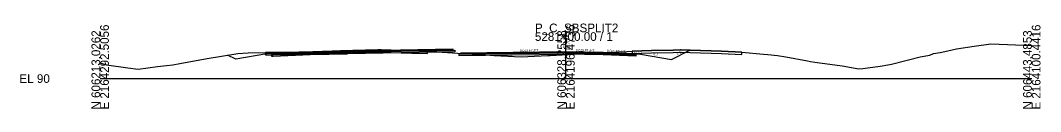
# Model space of a CAD drawing. Extents: x -26 to 1303, y -10 to 12033.
# Drawn here: x -25.7 to 302.8, y 990.3 to 1017.8 of the extents above; entities that cross this region are included whole.
import ezdxf

# ---------------------------------------------------------------- set-up
doc = ezdxf.new("R2010")
doc.units = 0
for name, color, linetype in [('RD_GPK_XS_Cell', 7, 'Continuous'), ('RD_XS_Base', 7, 'Continuous'), ('RD_XS_ExGround', 7, 'Continuous'), ('RD_XS_ExPaveRet', 7, 'Continuous'), ('RD_XS_Greenside', 7, 'Continuous'), ('RD_XS_Pave', 7, 'Continuous'), ('RD_XS_PaveOvlay_CP', 7, 'Continuous'), ('RD_XS_TieSlope', 7, 'Continuous'), ('RD_XS_TX_Elev_EX', 7, 'Continuous'), ('RD_XS_TX_Elev_PR', 7, 'Continuous'), ('RD_XS_TX_ShdSlope', 7, 'Continuous'), ('RD_XS_TX_Slope', 7, 'Continuous')]:
    doc.layers.add(name, color=color, linetype=linetype)

msp = doc.modelspace()

# ---------------------------------------------------------------- linework, layer by layer
at = {"layer": 'RD_GPK_XS_Cell'}
for p, q in [((150, 1000), (150, 1015)), ((0, 1000), (150, 1000)), ((150, 1000), (300, 1000))]:
    msp.add_line(p, q, dxfattribs=at)
at = {"layer": 'RD_XS_Base'}
for p, q in [((79.67, 1008.52), (113.67, 1009.2)), ((114.17, 1008.71), (79.67, 1008.02)), ((79.67, 1008.02), (79.67, 1008.68)), ((79.67, 1008.68), (79.67, 1008.68)), ((79.67, 1008.68), (79.67, 1008.68)), ((79.67, 1008.68), (79.67, 1008.52)), ((103.67, 1009), (103.67, 1009)), ((103.67, 1009), (103.67, 1009)), ((113.67, 1009.2), (113.67, 1009.2)), ((114.17, 1009.21), (114.17, 1008.71)), ((114.17, 1009.18), (114.17, 1009.18)), ((55.67, 1007.8), (55.17, 1007.78)), ((55.17, 1007.78), (55.17, 1007.78)), ((55.17, 1007.78), (55.17, 1007.28)), ((55.17, 1007.28), (55.67, 1007.3)), ((67.67, 1008.28), (55.67, 1007.8)), ((55.67, 1007.8), (55.67, 1007.8)), ((55.67, 1007.3), (67.67, 1007.78)), ((55.67, 1007.3), (55.67, 1007.3)), ((79.67, 1008.52), (67.67, 1008.28)), ((67.67, 1008.28), (67.67, 1008.28)), ((67.67, 1007.78), (79.67, 1008.02)), ((67.67, 1007.78), (67.67, 1007.78)), ((79.67, 1008.52), (79.67, 1008.52)), ((79.67, 1008.02), (79.67, 1008.52)), ((79.67, 1008.52), (79.67, 1008.52)), ((79.67, 1008.52), (79.67, 1008.52)), ((79.67, 1008.02), (79.67, 1008.02)), ((103.67, 1008.5), (103.67, 1008.5)), ((103.67, 1008.5), (103.67, 1008.5)), ((115.5, 1007.93), (115.5, 1007.43)), ((115.5, 1007.92), (115.5, 1007.92)), ((115.5, 1007.43), (149.99, 1007.88)), ((150, 1008.38), (116, 1007.94)), ((116, 1007.94), (116, 1007.94)), ((150, 1007.88), (150, 1008.54)), ((150, 1008.54), (150, 1008.54)), ((150, 1008.54), (150, 1008.54)), ((150, 1008.54), (150, 1008.38)), ((150, 1007.88), (150, 1008.38)), ((150, 1008.38), (150, 1008.38)), ((150, 1008.38), (150, 1008.38)), ((150, 1008.38), (150, 1008.38)), ((150, 1008.38), (162, 1008.14)), ((150, 1008.38), (150, 1008.38)), ((150, 1007.88), (150, 1007.88)), ((162, 1007.64), (150, 1007.88)), ((150, 1007.88), (150, 1007.88)), ((162, 1008.14), (162, 1008.14)), ((162, 1008.14), (172, 1007.74)), ((172.5, 1007.22), (162, 1007.64)), ((162, 1007.64), (162, 1007.64)), ((172, 1007.74), (172, 1007.74)), ((172, 1007.74), (172.5, 1007.72)), ((172.5, 1007.72), (172.5, 1007.72)), ((172.5, 1007.72), (172.5, 1007.22))]:
    msp.add_line(p, q, dxfattribs=at)
at = {"layer": 'RD_XS_ExGround'}
msp.add_lwpolyline([(0, 1005.15), (2.06, 1004.47), (8.93, 1003.52), (12.28, 1003.04), (18.45, 1003.86), (21.39, 1004.24), (23.36, 1004.5), (25.69, 1004.93), (34.43, 1006.49), (39.1, 1007.28), (44.31, 1008.17), (47.66, 1008.29), (53.22, 1008.45), (55.57, 1008.48), (63.95, 1008.59), (68.44, 1008.71), (74.67, 1008.88), (77.36, 1008.95), (89.46, 1009.27), (89.73, 1009.27), (90.52, 1009.27), (96.97, 1009.09), (100.35, 1009), (105.45, 1008.83), (108.29, 1008.68), (111.88, 1008.42), (122.97, 1007.71), (125.54, 1007.58), (126.92, 1007.48), (135.58, 1007.03), (144.13, 1007.46), (144.95, 1007.5), (160.49, 1008.3), (163.8, 1008.46), (167.1, 1008.66), (169.65, 1008.79), (171.33, 1008.88), (177.55, 1009.06), (184.52, 1009.24), (186.84, 1009.29), (187.03, 1009.28), (187.05, 1009.27), (187.1, 1009.28), (189.99, 1009.17), (200.07, 1008.84), (206.58, 1008.54), (213.66, 1007.89), (215, 1007.8), (218.09, 1007.49), (220.81, 1007.02), (227.74, 1005.74), (228.72, 1005.55), (230.14, 1005.35), (238.98, 1004.12), (244.33, 1003.12), (245.6, 1003.25), (251.21, 1004.07), (254.34, 1004.54), (254.83, 1004.68), (260.28, 1006.03), (264.04, 1007.01), (267.15, 1007.56), (268.34, 1008.08), (270.45, 1008.47), (273.96, 1009.2), (275.81, 1009.66), (281.41, 1010.47), (286.85, 1011.3), (292.21, 1011.04), (300, 1010.69)], dxfattribs=at)
at = {"layer": 'RD_XS_ExPaveRet'}
for points in [[(100.35, 1009), (96.97, 1009.09), (90.52, 1009.27), (90.52, 1009.27), (90.52, 1009.27), (90.52, 1009.27), (89.73, 1009.27), (89.46, 1009.27), (89.46, 1009.27), (89.46, 1009.27), (77.36, 1008.95), (77.36, 1008.95), (74.67, 1008.88), (68.44, 1008.71), (68.44, 1008.71), (63.95, 1008.59), (63.95, 1008.59), (55.57, 1008.48), (55.57, 1008.48), (53.22, 1008.45), (53.22, 1008.45), (53.22, 1008.45), (53.22, 1007.7), (53.22, 1007.7), (55.57, 1007.73), (55.57, 1007.73), (63.95, 1007.84), (63.95, 1007.84), (68.44, 1007.96), (68.44, 1007.96), (74.67, 1008.13), (77.36, 1008.2), (77.36, 1008.2), (89.46, 1008.52), (89.46, 1008.52), (89.46, 1008.52), (89.73, 1008.52), (90.52, 1008.52), (90.52, 1008.52), (90.52, 1008.52), (90.52, 1008.52), (96.97, 1008.34), (100.35, 1008.25), (100.35, 1008.25), (105.45, 1008.08), (105.45, 1008.83), (105.45, 1008.83), (100.35, 1009), (100.35, 1009)], [(100.35, 1009), (96.97, 1009.09), (90.52, 1009.27), (89.73, 1009.27), (89.46, 1009.27), (77.36, 1008.95), (74.67, 1008.88), (68.44, 1008.71), (63.95, 1008.59), (55.57, 1008.48), (53.22, 1008.45), (53.22, 1007.7), (55.57, 1007.73), (63.95, 1007.84), (68.44, 1007.96), (74.67, 1008.13), (77.36, 1008.2), (89.46, 1008.52), (89.73, 1008.52), (90.52, 1008.52), (96.97, 1008.34), (100.35, 1008.25), (105.45, 1008.08), (105.45, 1008.83), (100.35, 1009)], [(200.07, 1008.84), (189.99, 1009.17), (189.99, 1009.17), (187.1, 1009.28), (187.1, 1009.28), (187.05, 1009.27), (187.03, 1009.28), (186.84, 1009.29), (186.84, 1009.29), (186.84, 1009.29), (186.84, 1009.29), (184.52, 1009.24), (184.52, 1009.24), (177.55, 1009.06), (177.55, 1009.06), (177.55, 1009.06), (171.33, 1008.88), (171.33, 1008.88), (171.33, 1008.13), (177.55, 1008.31), (177.55, 1008.31), (177.55, 1008.31), (184.52, 1008.49), (184.52, 1008.49), (186.84, 1008.54), (186.84, 1008.54), (186.84, 1008.54), (186.84, 1008.54), (187.03, 1008.53), (187.05, 1008.52), (187.1, 1008.53), (187.1, 1008.53), (189.99, 1008.42), (189.99, 1008.42), (200.07, 1008.09), (200.07, 1008.09), (206.58, 1007.79), (206.58, 1008.54), (206.58, 1008.54), (200.07, 1008.84), (200.07, 1008.84)], [(200.07, 1008.84), (189.99, 1009.17), (187.1, 1009.28), (187.05, 1009.27), (187.03, 1009.28), (186.84, 1009.29), (184.52, 1009.24), (177.55, 1009.06), (171.33, 1008.88), (171.33, 1008.13), (177.55, 1008.31), (184.52, 1008.49), (186.84, 1008.54), (187.03, 1008.53), (187.05, 1008.52), (187.1, 1008.53), (189.99, 1008.42), (200.07, 1008.09), (206.58, 1007.79), (206.58, 1008.54), (200.07, 1008.84)]]:
    msp.add_lwpolyline(points, dxfattribs=at)
at = {"layer": 'RD_XS_Greenside'}
for p, q in [((184, 1006.23), (189.89, 1009.17)), ((43.67, 1006.29), (41.03, 1007.61)), ((53.67, 1007.96), (43.67, 1006.29)), ((174, 1007.9), (184, 1006.23))]:
    msp.add_line(p, q, dxfattribs=at)
at = {"layer": 'RD_XS_Pave'}
for p, q in [((67.67, 1008.6), (55.67, 1008.12)), ((79.67, 1008.84), (67.67, 1008.6)), ((67.67, 1008.44), (79.67, 1008.68)), ((79.67, 1008.68), (67.67, 1008.44)), ((67.67, 1008.6), (67.67, 1008.6)), ((113.67, 1009.52), (79.67, 1008.84)), ((113.67, 1009.36), (79.67, 1008.68)), ((79.67, 1008.68), (113.67, 1009.36)), ((79.67, 1008.52), (114.17, 1009.21)), ((79.67, 1008.84), (79.67, 1008.84)), ((79.67, 1008.52), (79.67, 1008.68)), ((79.67, 1008.68), (79.67, 1008.68)), ((79.67, 1008.68), (79.67, 1008.68)), ((79.67, 1008.68), (79.67, 1008.68)), ((79.67, 1008.68), (79.67, 1008.68)), ((79.67, 1008.68), (79.67, 1008.52)), ((79.67, 1008.68), (79.67, 1008.68)), ((103.67, 1009.32), (103.67, 1009.32)), ((103.67, 1009.32), (103.67, 1009.32)), ((103.67, 1009.16), (103.67, 1009.16)), ((103.67, 1009.16), (103.67, 1009.16)), ((103.67, 1009.16), (103.67, 1009.16)), ((103.67, 1009.16), (103.67, 1009.16)), ((103.67, 1009), (103.67, 1009)), ((103.67, 1009), (103.67, 1009)), ((113.67, 1009.36), (113.67, 1009.52)), ((113.67, 1009.52), (113.67, 1009.52)), ((113.67, 1009.2), (113.67, 1009.36)), ((113.67, 1009.36), (113.67, 1009.36)), ((150, 1008.7), (116, 1008.25)), ((162, 1008.46), (150, 1008.7)), ((150, 1008.7), (150, 1008.7)), ((150, 1008.7), (150, 1008.7)), ((55.67, 1007.96), (67.67, 1008.44)), ((67.67, 1008.44), (55.67, 1007.96)), ((55.67, 1007.8), (67.67, 1008.28)), ((55.67, 1008.12), (55.67, 1008.12)), ((55.67, 1008.12), (55.67, 1007.96)), ((55.67, 1007.96), (55.67, 1007.96)), ((55.67, 1007.96), (55.67, 1007.8)), ((67.67, 1008.28), (79.67, 1008.52)), ((67.67, 1008.44), (67.67, 1008.44)), ((67.67, 1008.44), (67.67, 1008.44)), ((67.67, 1008.28), (67.67, 1008.28)), ((79.67, 1008.52), (79.67, 1008.52)), ((79.67, 1008.52), (79.67, 1008.52)), ((115.5, 1007.93), (150, 1008.38)), ((150, 1008.54), (116, 1008.09)), ((116, 1008.09), (150, 1008.54)), ((116, 1008.25), (116, 1008.25)), ((116, 1008.25), (116, 1008.09)), ((116, 1008.09), (116, 1008.09)), ((116, 1008.09), (116, 1007.94)), ((150, 1008.38), (150, 1008.54)), ((150, 1008.54), (150, 1008.54)), ((150, 1008.54), (150, 1008.54)), ((150, 1008.54), (150, 1008.54)), ((150, 1008.54), (150, 1008.54)), ((150, 1008.54), (162, 1008.3)), ((162, 1008.3), (150, 1008.54)), ((150, 1008.54), (150, 1008.54)), ((150, 1008.54), (150, 1008.54)), ((150, 1008.54), (150, 1008.54)), ((150, 1008.54), (150, 1008.38)), ((150, 1008.38), (150, 1008.38)), ((150, 1008.38), (150, 1008.38)), ((150, 1008.38), (150, 1008.38)), ((150, 1008.38), (162, 1008.14)), ((172, 1008.06), (162, 1008.46)), ((162, 1008.46), (162, 1008.46)), ((162, 1008.3), (162, 1008.3)), ((162, 1008.3), (172, 1007.9)), ((172, 1007.9), (162, 1008.3)), ((162, 1008.3), (162, 1008.3)), ((162, 1008.14), (172, 1007.74)), ((162, 1008.14), (162, 1008.14)), ((172, 1007.9), (172, 1008.06)), ((172, 1008.06), (172, 1008.06)), ((172, 1007.74), (172, 1007.9)), ((172, 1007.9), (172, 1007.9))]:
    msp.add_line(p, q, dxfattribs=at)
at = {"layer": 'RD_XS_PaveOvlay_CP'}
for p, q in [((67.67, 1008.6), (55.67, 1008.12)), ((79.67, 1008.84), (67.67, 1008.6)), ((67.67, 1008.6), (67.67, 1008.6)), ((113.67, 1009.52), (79.67, 1008.84)), ((79.67, 1008.84), (79.67, 1008.84)), ((103.67, 1009.32), (103.67, 1009.32)), ((103.67, 1009.32), (103.67, 1009.32)), ((150, 1008.7), (116, 1008.25)), ((162, 1008.46), (150, 1008.7)), ((150, 1008.7), (150, 1008.7)), ((150, 1008.7), (150, 1008.7)), ((172, 1008.06), (162, 1008.46)), ((162, 1008.46), (162, 1008.46))]:
    msp.add_line(p, q, dxfattribs=at)
at = {"layer": 'RD_XS_TieSlope'}
for p, q in [((55.67, 1008.12), (53.67, 1007.96)), ((172, 1008.06), (174, 1007.9))]:
    msp.add_line(p, q, dxfattribs=at)

# ---------------------------------------------------------------- texts
at = {"layer": 'RD_GPK_XS_Cell'}
for s, p in [('N 606213.0262', (0, 990)), ('E 2164292.5056', (2.8, 990)), ('N 606328.2558', (150, 990)), ('E 2164196.4736', (152.8, 990)), ('N 606443.4853', (300, 990)), ('E 2164100.4416', (302.8, 990))]:
    msp.add_text(s, height=2.8, rotation=90, dxfattribs=at).set_placement(p)
for s, p in [('P_C_SBSPLIT2', (140, 1015)), ('5281+00.00 / 1', (140, 1012.2)), ('EL 90', (-26, 998.6))]:
    msp.add_text(s, height=2.8, dxfattribs=at).set_placement(p)
at = {"layer": 'RD_XS_TX_Elev_EX'}
msp.add_text('97.76', height=0.6, rotation=90, dxfattribs=at).set_placement((149.64, 1009.86))
at = {"layer": 'RD_XS_TX_Elev_PR'}
msp.add_text('98.70', height=1, rotation=90, dxfattribs=at).set_placement((151.19, 1009.19))
at = {"layer": 'RD_XS_TX_ShdSlope'}
msp.add_text('12.5:1', height=0.75, rotation=355.4261, dxfattribs=at).set_placement((171.8, 1008.31))
at = {"layer": 'RD_XS_TX_Slope'}
for s, rotation, p in [('0.013 FT./FT.', 0.7448, (135.16, 1008.72)), ('0.020 FT./FT.', 358.8542, (153.16, 1008.85)), ('0.040 FT./FT.', 357.7094, (163.17, 1008.63)), ('2:1', 26.5651, (185.86, 1007.59)), ('6:1', 350.5358, (178.13, 1007.61))]:
    msp.add_text(s, height=0.75, rotation=rotation, dxfattribs=at).set_placement(p)

doc.saveas('drawing.dxf')
